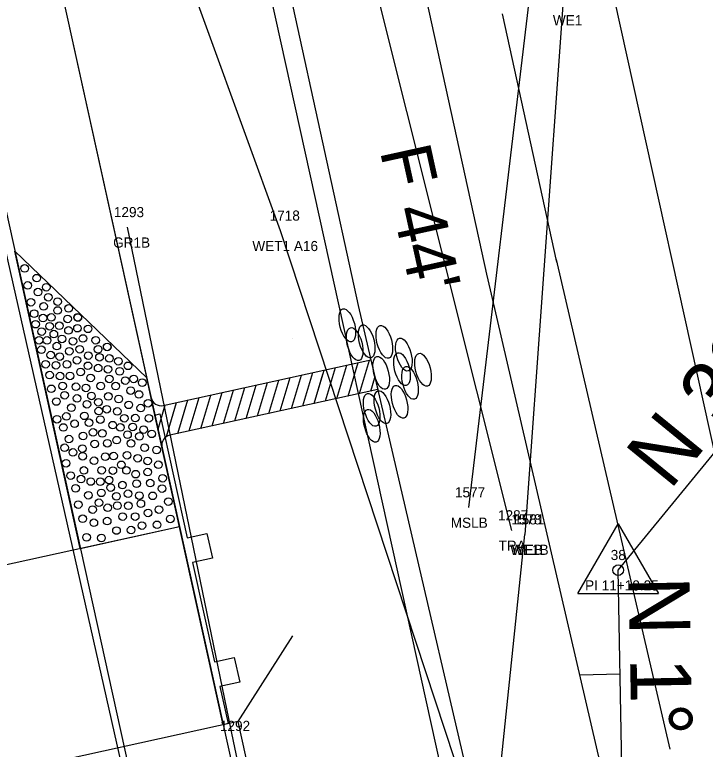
# Model space of a CAD drawing. Extents: x 2520975 to 2526538, y 881018 to 888064.
# Drawn here: x 2523776.7 to 2523844.7, y 885185.4 to 885257.8 of the extents above; entities that cross this region are included whole.
import ezdxf

# ---------------------------------------------------------------- set-up
doc = ezdxf.new("R2010")
doc.units = 0
for name, color, linetype in [('RD_EV_JurisArea', 7, 'Continuous'), ('RD_EX_DV_Prop', 7, 'Continuous'), ('RD_EX_GuardRail', 7, 'Continuous'), ('RD_EX_GuardRail_txCode', 7, 'Continuous'), ('RD_EX_H2O', 7, 'Continuous'), ('RD_EX_H2O_txCode', 7, 'Continuous'), ('RD_EX_H2O_WetLd_txCode', 7, 'Continuous'), ('RD_EX_Misc', 7, 'Continuous'), ('RD_EX_Misc_txCode', 7, 'Continuous'), ('RD_EX_Road', 7, 'Continuous'), ('RD_EX_RW', 7, 'Continuous'), ('RD_EX_VEG', 7, 'Continuous'), ('RD_EX_VEG_txCode', 7, 'Continuous'), ('RD_HC_Cl', 7, 'Continuous'), ('RD_HC_Data', 7, 'Continuous'), ('RD_HC_Data_Tic', 7, 'Continuous'), ('RD_HC_txCode', 7, 'Continuous'), ('RD_PD_BCA', 7, 'Continuous'), ('RD_PD_Bridge', 7, 'Continuous'), ('RD_PD_CstnLmt', 7, 'Continuous'), ('RD_PD_DR_ErosCtrl', 7, 'Continuous'), ('RD_PD_Final_TrvlWay', 7, 'Continuous'), ('RD_PD_GR', 7, 'Continuous'), ('RD_PD_PaveShd', 7, 'Continuous'), ('RD_SMD_Locator', 7, 'Continuous')]:
    doc.layers.add(name, color=color, linetype=linetype)

# ---------------------------------------------------------------- blocks, each defined once
blk = doc.blocks.new('TBC1')
at = {"layer": 'RD_PD_GR'}
blk.add_lwpolyline([(12.5, 2.5), (15, 2.5), (15, 0.492), (25, 0.492), (25, 2.5), (27.5, 2.5), (27.5, 0.492), (31.25, 0.492), (31.25, 0), (0, 0), (0, 0.492), (12.5, 0.492)], close=True, dxfattribs=at)

msp = doc.modelspace()

# ---------------------------------------------------------------- linework, layer by layer
at = {"layer": 'RD_EV_JurisArea'}
msp.add_lwpolyline([(2523761.167, 885134.03), (2523808.209, 885149.207), (2523821.914, 885178.637), (2523802.851, 885236.548), (2523777.81, 885305.562), (2523748.196, 885444.322), (2523730.68, 885516.876), (2523708.637, 885617.3), (2523698.714, 885662.019), (2523727.827, 885665.815), (2523757.297, 885671.751)], dxfattribs=at)
at = {"layer": 'RD_EX_DV_Prop'}
msp.add_line((2523830.151, 885284.722), (2523894.666, 884991.741), dxfattribs=at)
at = {"layer": 'RD_EX_GuardRail'}
msp.add_lwpolyline([(2523803.786, 885159.912), (2523798.239, 885186.256), (2523787.795, 885236.892)], dxfattribs=at)
at = {"layer": 'RD_EX_H2O'}
for points in [[(2524064.856, 885165.15), (2524036.37, 885213.784), (2524057.223, 885252.722), (2524031.954, 885291.634), (2523983.255, 885326.297), (2523940.609, 885311.826), (2523904.837, 885305.013), (2523874.983, 885272.096), (2523850.319, 885280.241), (2523830.665, 885258.799), (2523826.928, 885206.612)], [(2523738.909, 885147.498), (2523743.695, 885138.843), (2523816.359, 885152.29), (2523822.427, 885163.299), (2523826.928, 885206.612)]]:
    msp.add_lwpolyline(points, dxfattribs=at)
at = {"layer": 'RD_EX_Misc'}
msp.add_lwpolyline([(2524066.305, 885165.351), (2524037.301, 885214.147), (2524057.946, 885253.065), (2524039.523, 885283.168), (2524032.922, 885292.565), (2523983.53, 885327.977), (2523940.238, 885313.274), (2523904.134, 885306.246), (2523874.86, 885272.666), (2523849.958, 885282.507), (2523827.651, 885261.934), (2523821.385, 885209.277)], dxfattribs=at)
at = {"layer": 'RD_EX_Road'}
msp.add_line((2523792.777, 885159.311), (2523771.239, 885254.787), dxfattribs=at)
at = {"layer": 'RD_EX_RW'}
msp.add_line((2523830.151, 885284.719), (2523894.667, 884991.738), dxfattribs=at)
at = {"layer": 'RD_EX_VEG'}
msp.add_lwpolyline([(2523825.623, 885207.01), (2523811.867, 885262.105), (2523733.022, 885654.224), (2523687.107, 885876.236)], dxfattribs=at)
at = {"layer": 'RD_HC_Cl'}
for p, q in [((2523662.651, 885798.932), (2524219.244, 883271.288)), ((2523836.106, 885203.1), (2523883.663, 885261.233)), ((2523837.18, 885148.323), (2523836.106, 885203.1))]:
    msp.add_line(p, q, dxfattribs=at)
at = {"layer": 'RD_HC_Data'}
for p, q in [((2523832.135, 885200.807), (2523836.107, 885207.686)), ((2523836.107, 885207.686), (2523840.076, 885200.807)), ((2523832.135, 885200.807), (2523840.076, 885200.807))]:
    msp.add_line(p, q, dxfattribs=at)
msp.add_circle((2523836.106, 885203.1), 0.529, dxfattribs=at)
at = {"layer": 'RD_HC_Data_Tic'}
msp.add_line((2523836.307, 885192.845), (2523832.308, 885192.766), dxfattribs=at)
at = {"layer": 'RD_PD_BCA'}
for p, q in [((2523824.701, 885257.92), (2523830.049, 885233.47)), ((2523829.993, 885233.72), (2523841.201, 885185.449))]:
    msp.add_line(p, q, dxfattribs=at)
at = {"layer": 'RD_PD_Bridge'}
for p, q in [((2523749.936, 885197.941), (2523792.907, 885207.403)), ((2523797.208, 885187.871), (2523792.907, 885207.403)), ((2523798.673, 885188.194), (2523804.058, 885196.62))]:
    msp.add_line(p, q, dxfattribs=at)
for points in [[(2523798.673, 885188.194), (2523752.772, 885178.086)], [(2523826.629, 885061.235), (2523798.673, 885188.194)]]:
    msp.add_lwpolyline(points, dxfattribs=at)
at = {"layer": 'RD_PD_CstnLmt'}
for p, q in [((2523789.142, 885326.887), (2523810.511, 885229.196)), ((2523810.511, 885229.196), (2523821.719, 885180.926))]:
    msp.add_line(p, q, dxfattribs=at)
at = {"layer": 'RD_PD_DR_ErosCtrl'}
for p, q in [((2523801.841, 885329.665), (2523823.211, 885231.974)), ((2523823.174, 885232.137), (2523834.383, 885183.866))]:
    msp.add_line(p, q, dxfattribs=at)
at = {"layer": 'RD_PD_Final_TrvlWay'}
for p, q in [((2523712.872, 885663.865), (2524066.737, 884056.869)), ((2523720.239, 885490.907), (2524037.438, 884050.417))]:
    msp.add_line(p, q, dxfattribs=at)
at = {"layer": 'RD_PD_GR'}
msp.add_line((2523742.101, 885438.126), (2523790.488, 885218.39), dxfattribs=at)
at = {"layer": 'RD_PD_PaveShd'}
for p, q in [((2523776.689, 885234.551), (2523789.681, 885222.052)), ((2523783.141, 885205.253), (2523776.689, 885234.551)), ((2523791.303, 885219.337), (2523811.757, 885223.83)), ((2523808.404, 885220.022), (2523809.388, 885223.309)), ((2523808.404, 885220.022), (2523809.388, 885223.309)), ((2523809.521, 885220.267), (2523810.505, 885223.555)), ((2523810.638, 885220.513), (2523811.622, 885223.8)), ((2523810.638, 885220.513), (2523811.622, 885223.8)), ((2523811.757, 885223.83), (2523812.436, 885220.907)), ((2523806.169, 885219.531), (2523807.153, 885222.819)), ((2523807.287, 885219.776), (2523808.271, 885223.064)), ((2523807.287, 885219.776), (2523808.271, 885223.064)), ((2523809.521, 885220.267), (2523810.384, 885223.15)), ((2523790.326, 885219.122), (2523789.681, 885222.052)), ((2523802.818, 885218.795), (2523803.801, 885222.082)), ((2523802.818, 885218.795), (2523803.801, 885222.082)), ((2523803.935, 885219.04), (2523804.919, 885222.328)), ((2523803.935, 885219.04), (2523804.919, 885222.328)), ((2523805.052, 885219.286), (2523806.036, 885222.573)), ((2523805.052, 885219.286), (2523806.036, 885222.573)), ((2523806.169, 885219.531), (2523807.032, 885222.413)), ((2523811.756, 885220.758), (2523812.158, 885222.103)), ((2523811.756, 885220.758), (2523812.158, 885222.103)), ((2523799.466, 885218.058), (2523800.45, 885221.346)), ((2523799.466, 885218.058), (2523800.45, 885221.346)), ((2523800.583, 885218.304), (2523801.567, 885221.591)), ((2523800.583, 885218.304), (2523801.567, 885221.591)), ((2523801.7, 885218.549), (2523802.684, 885221.837)), ((2523801.7, 885218.549), (2523802.684, 885221.837)), ((2523812.436, 885220.907), (2523791.949, 885216.407)), ((2523796.114, 885217.322), (2523797.098, 885220.61)), ((2523797.231, 885217.568), (2523798.215, 885220.855)), ((2523797.231, 885217.568), (2523798.215, 885220.855)), ((2523798.348, 885217.813), (2523799.332, 885221.101)), ((2523798.348, 885217.813), (2523799.332, 885221.101)), ((2523792.762, 885216.586), (2523793.746, 885219.874)), ((2523792.762, 885216.586), (2523793.746, 885219.874)), ((2523793.879, 885216.831), (2523794.863, 885220.119)), ((2523793.879, 885216.831), (2523794.863, 885220.119)), ((2523794.997, 885217.077), (2523795.981, 885220.364)), ((2523794.997, 885217.077), (2523795.981, 885220.364)), ((2523790.971, 885216.193), (2523790.326, 885219.122)), ((2523790.796, 885216.992), (2523791.511, 885219.383)), ((2523791.625, 885216.273), (2523792.629, 885219.628)), ((2523792.907, 885207.403), (2523790.971, 885216.193)), ((2523783.141, 885205.253), (2523792.907, 885207.403))]:
    msp.add_line(p, q, dxfattribs=at)
for centre in [(2523777.666, 885232.841), (2523778.856, 885231.882), (2523778.856, 885231.882), (2523777.968, 885231.167), (2523777.968, 885231.167), (2523779.793, 885230.988), (2523779.793, 885230.988), (2523778.977, 885230.511), (2523778.977, 885230.511), (2523778.285, 885229.502), (2523778.285, 885229.502), (2523779.981, 885229.998), (2523779.981, 885229.998), (2523780.904, 885229.572), (2523779.522, 885229.096), (2523779.522, 885229.096), (2523781.994, 885228.895), (2523781.994, 885228.895), (2523778.599, 885228.38), (2523778.599, 885228.38), (2523780.286, 885228.017), (2523780.286, 885228.017), (2523780.902, 885228.695), (2523780.902, 885228.695), (2523782.878, 885228.022), (2523782.902, 885227.998), (2523778.738, 885227.346), (2523778.738, 885227.346), (2523779.472, 885227.942), (2523779.472, 885227.942), (2523781.895, 885227.867), (2523781.895, 885227.867), (2523779.333, 885226.612), (2523779.333, 885226.612), (2523780.119, 885227.145), (2523780.119, 885227.145), (2523781.078, 885227.19), (2523781.078, 885227.19), (2523781.98, 885226.731), (2523781.98, 885226.731), (2523782.865, 885226.95), (2523782.865, 885226.95), (2523783.909, 885226.886), (2523783.909, 885226.886), (2523780.537, 885226.371), (2523780.537, 885226.371), (2523781.34, 885225.894), (2523781.34, 885225.894), (2523783.396, 885225.935), (2523783.396, 885225.935), (2523779.08, 885225.767), (2523779.08, 885225.767), (2523779.876, 885225.741), (2523779.876, 885225.741), (2523780.831, 885225.184), (2523780.831, 885225.184), (2523782.41, 885225.668), (2523782.41, 885225.668), (2523784.667, 885225.761), (2523784.667, 885225.761), (2523785.786, 885225.108), (2523785.797, 885225.105), (2523779.317, 885224.822), (2523779.317, 885224.822), (2523782.05, 885224.678), (2523782.05, 885224.678), (2523783.094, 885224.873), (2523783.094, 885224.873), (2523784.896, 885224.866), (2523784.896, 885224.866), (2523780.235, 885224.299), (2523780.235, 885224.299), (2523781.114, 885224.154), (2523781.114, 885224.154), (2523782.805, 885223.79), (2523782.805, 885223.79), (2523783.924, 885224.247), (2523783.924, 885224.247), (2523785.033, 885224.081), (2523785.033, 885224.081), (2523786.014, 885223.973), (2523786.014, 885223.973), (2523786.9, 885223.688), (2523786.9, 885223.688), (2523779.722, 885223.401), (2523779.722, 885223.401), (2523780.743, 885223.296), (2523780.743, 885223.296), (2523781.821, 885223.387), (2523781.821, 885223.387), (2523783.893, 885223.243), (2523783.893, 885223.243), (2523784.902, 885223.024), (2523784.902, 885223.024), (2523787.841, 885223.241), (2523787.841, 885223.241), (2523780.123, 885222.324), (2523780.123, 885222.324), (2523781.15, 885222.234), (2523781.15, 885222.234), (2523782.128, 885222.251), (2523782.128, 885222.251), (2523783.172, 885222.632), (2523783.172, 885222.632), (2523785.859, 885222.903), (2523785.859, 885222.903), (2523787.018, 885222.701), (2523787.018, 885222.701), (2523784.155, 885222.048), (2523784.155, 885222.048), (2523785.988, 885221.955), (2523785.988, 885221.955), (2523787.572, 885221.791), (2523787.572, 885221.791), (2523788.407, 885221.955), (2523788.407, 885221.955), (2523789.246, 885221.58), (2523789.246, 885221.58), (2523789.246, 885221.58), (2523780.277, 885220.975), (2523780.277, 885220.975), (2523781.397, 885221.261), (2523781.397, 885221.261), (2523782.715, 885221.176), (2523782.715, 885221.176), (2523783.693, 885221.06), (2523783.693, 885221.06), (2523785.157, 885221.252), (2523785.157, 885221.252), (2523786.624, 885221.248), (2523786.624, 885221.248), (2523788.104, 885220.805), (2523788.104, 885220.805), (2523781.597, 885220.343), (2523781.597, 885220.343), (2523782.826, 885220.027), (2523782.826, 885220.027), (2523784.244, 885220.275), (2523784.244, 885220.275), (2523785.903, 885220.223), (2523785.903, 885220.223), (2523788.918, 885220.417), (2523788.918, 885220.417), (2523780.792, 885219.725), (2523780.792, 885219.725), (2523783.793, 885219.459), (2523783.793, 885219.459), (2523784.927, 885219.657), (2523784.927, 885219.657), (2523786.923, 885219.97), (2523786.923, 885219.97), (2523787.909, 885219.396), (2523787.909, 885219.396), (2523789.821, 885219.548), (2523789.821, 885219.548), (2523782.262, 885219.11), (2523782.262, 885219.11), (2523784.954, 885218.78), (2523784.954, 885218.78), (2523785.754, 885218.965), (2523785.754, 885218.965), (2523786.785, 885218.75), (2523786.785, 885218.75), (2523789.097, 885219.082), (2523789.097, 885219.082), (2523780.846, 885217.973), (2523780.846, 885217.973), (2523781.777, 885218.252), (2523781.777, 885218.252), (2523783.552, 885218.311), (2523783.552, 885218.311), (2523785.118, 885217.946), (2523785.118, 885217.946), (2523787.474, 885218.079), (2523787.474, 885218.079), (2523788.551, 885218.087), (2523788.551, 885218.087), (2523789.893, 885218.079), (2523789.893, 885218.079), (2523781.472, 885217.165), (2523781.472, 885217.165), (2523782.574, 885217.528), (2523782.574, 885217.528), (2523784.012, 885217.636), (2523784.012, 885217.636), (2523786.338, 885217.395), (2523786.338, 885217.395), (2523787.097, 885217.168), (2523787.097, 885217.168), (2523788.312, 885217.218), (2523788.312, 885217.218), (2523784.4, 885216.674), (2523784.4, 885216.674), (2523785.31, 885216.586), (2523785.31, 885216.586), (2523787.793, 885216.457), (2523787.793, 885216.457), (2523789.373, 885216.963), (2523789.373, 885216.963), (2523790.175, 885216.537), (2523790.175, 885216.537), (2523782.019, 885216.02), (2523782.019, 885216.02), (2523783.413, 885216.326), (2523783.413, 885216.326), (2523786.722, 885215.916), (2523786.722, 885215.916), (2523788.963, 885216.293), (2523788.963, 885216.293), (2523781.595, 885215.164), (2523783.351, 885215.084), (2523783.351, 885215.084), (2523784.565, 885215.548), (2523784.565, 885215.548), (2523785.804, 885215.611), (2523785.804, 885215.611), (2523788.136, 885215.596), (2523788.136, 885215.596), (2523789.478, 885215.174), (2523789.478, 885215.174), (2523782.41, 885214.704), (2523782.41, 885214.704), (2523783.374, 885214.333), (2523783.374, 885214.333), (2523785.594, 885214.289), (2523785.594, 885214.289), (2523786.419, 885214.352), (2523786.419, 885214.352), (2523787.746, 885214.431), (2523787.746, 885214.431), (2523790.65, 885214.948), (2523790.65, 885214.948), (2523781.741, 885213.643), (2523781.741, 885213.643), (2523784.503, 885213.892), (2523784.503, 885213.892), (2523788.795, 885214.138), (2523788.795, 885214.138), (2523789.769, 885213.867), (2523789.769, 885213.867), (2523783.492, 885212.933), (2523783.492, 885212.933), (2523785.234, 885212.949), (2523785.234, 885212.949), (2523786.348, 885212.919), (2523786.348, 885212.919), (2523787.173, 885213.486), (2523787.173, 885213.486), (2523787.691, 885212.938), (2523787.691, 885212.938), (2523790.833, 885213.487), (2523790.833, 885213.487), (2523782.204, 885212.429), (2523782.204, 885212.429), (2523783.214, 885212.079), (2523783.214, 885212.079), (2523788.593, 885212.565), (2523788.593, 885212.565), (2523789.79, 885212.765), (2523789.79, 885212.765), (2523791.249, 885212.164), (2523791.249, 885212.164), (2523784.178, 885211.839), (2523784.178, 885211.839), (2523785.102, 885211.825), (2523785.102, 885211.825), (2523785.978, 885211.982), (2523785.978, 885211.982), (2523787.297, 885211.485), (2523787.297, 885211.485), (2523788.684, 885211.628), (2523788.684, 885211.628), (2523790.024, 885211.682), (2523790.024, 885211.682), (2523782.68, 885211.17), (2523782.68, 885211.17), (2523785.213, 885210.723), (2523785.213, 885210.723), (2523786.142, 885211.239), (2523787.851, 885210.633), (2523787.851, 885210.633), (2523791.192, 885211.147), (2523791.192, 885211.147), (2523783.942, 885210.483), (2523783.942, 885210.483), (2523786.703, 885210.381), (2523786.703, 885210.381), (2523788.957, 885210.451), (2523788.957, 885210.451), (2523790.274, 885210.429), (2523790.274, 885210.429), (2523782.943, 885209.562), (2523782.943, 885209.562), (2523784.978, 885209.753), (2523784.978, 885209.753), (2523785.848, 885209.251), (2523785.848, 885209.251), (2523786.792, 885209.459), (2523786.792, 885209.459), (2523787.872, 885209.452), (2523787.872, 885209.452), (2523789.105, 885209.656), (2523789.105, 885209.656), (2523791.821, 885209.863), (2523791.821, 885209.863), (2523784.349, 885209.079), (2523784.349, 885209.079), (2523789.812, 885208.748), (2523789.812, 885208.748), (2523790.88, 885209.07), (2523790.88, 885209.07), (2523783.374, 885208.172), (2523783.374, 885208.172), (2523784.477, 885207.78), (2523784.477, 885207.78), (2523785.788, 885207.946), (2523785.788, 885207.946), (2523787.304, 885208.382), (2523787.304, 885208.382), (2523788.545, 885208.383), (2523788.545, 885208.383), (2523792.011, 885208.152), (2523792.011, 885208.152), (2523792.011, 885208.152), (2523786.707, 885207.01), (2523786.707, 885207.01), (2523788.147, 885207.055), (2523788.147, 885207.055), (2523789.211, 885207.501), (2523789.211, 885207.501), (2523790.7, 885207.573), (2523790.7, 885207.573), (2523783.756, 885206.341), (2523783.756, 885206.341), (2523785.225, 885206.274), (2523785.225, 885206.274)]:
    msp.add_circle(centre, 0.375, dxfattribs=at)
for centre, start, end in [((2523791.088, 885220.314), 192.41848, 282.38886), ((2523792.163, 885215.431), 102.38886, 192.41848)]:
    msp.add_arc(centre, 1, start, end, dxfattribs=at)
for centre in [(2523809.435, 885227.232), (2523810.164, 885225.383), (2523811.34, 885225.65), (2523811.34, 885225.65), (2523813.084, 885225.604), (2523813.084, 885225.604), (2523815.003, 885224.349), (2523815.003, 885224.349), (2523812.773, 885222.548), (2523812.773, 885222.548), (2523814.822, 885222.914), (2523814.822, 885222.914), (2523816.892, 885222.854), (2523816.892, 885222.854), (2523815.615, 885221.56), (2523815.615, 885221.56), (2523814.581, 885219.698), (2523814.581, 885219.698), (2523811.838, 885218.904), (2523811.838, 885218.904), (2523812.892, 885219.169), (2523812.892, 885219.169), (2523811.845, 885217.332), (2523811.845, 885217.332)]:
    msp.add_ellipse(centre, major_axis=(-0.426, 1.616), ratio=0.429445, dxfattribs=at)
at = {"layer": 'RD_SMD_Locator'}
for centre in [(2523787.795, 885236.892), (2523802.851, 885236.548), (2523804.069, 885225.964), (2523821.385, 885209.277), (2523825.623, 885207.01), (2523826.928, 885206.612), (2523826.928, 885206.612), (2523836.106, 885203.1), (2523798.239, 885186.256)]:
    msp.add_circle(centre, 0.001, dxfattribs=at)

# ---------------------------------------------------------------- block references
at = {"layer": 'RD_PD_Bridge', "rotation": -77.58151740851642}
msp.add_blockref('TBC1', (2523790.488, 885218.39), dxfattribs=at)

# ---------------------------------------------------------------- texts
at = {"layer": 'RD_EX_GuardRail_txCode'}
for s, p in [('1293', (2523786.449, 885237.892)), ('GR1B', (2523786.378, 885234.892)), ('1292', (2523796.892, 885187.256))]:
    msp.add_text(s, height=1, dxfattribs=at).set_placement(p)
at = {"layer": 'RD_EX_H2O_txCode'}
for s, p in [('WE1', (2523829.681, 885256.799)), ('1578', (2523825.582, 885207.612)), ('1581', (2523825.865, 885207.612)), ('WE1B', (2523825.471, 885204.612)), ('WEB', (2523825.637, 885204.612))]:
    msp.add_text(s, height=1, dxfattribs=at).set_placement(p)
at = {"layer": 'RD_EX_H2O_WetLd_txCode'}
for s, p in [('1718', (2523801.788, 885237.548)), ('WET1 A16', (2523800.087, 885234.548))]:
    msp.add_text(s, height=1, dxfattribs=at).set_placement(p)
at = {"layer": 'RD_EX_Misc_txCode'}
for s, p in [('1577', (2523820.038, 885210.277)), ('MSLB', (2523819.621, 885207.277))]:
    msp.add_text(s, height=1, dxfattribs=at).set_placement(p)
at = {"layer": 'RD_EX_VEG_txCode'}
for s, p in [('1287', (2523824.276, 885208.01)), ('TRA', (2523824.339, 885205.01))]:
    msp.add_text(s, height=1, dxfattribs=at).set_placement(p)
at = {"layer": 'RD_HC_Data'}
for s, rotation, p in [('N 39%%d 17\' 08" E', 50.71443, (2523841.195, 885210.9)), ('N 1%%d 07\' 21" W', 271.12261, (2523837.119, 885202.44))]:
    msp.add_text(s, height=6, rotation=rotation, dxfattribs=at).set_placement(p)
at = {"layer": 'RD_HC_txCode'}
for s, p in [('38', (2523835.374, 885204.1)), ('PI 11+10.25', (2523832.854, 885201.1))]:
    msp.add_text(s, height=1, dxfattribs=at).set_placement(p)
at = {"layer": 'RD_PD_CstnLmt'}
msp.add_text("F 44'", height=5, rotation=282.41848, dxfattribs=at).set_placement((2523812.626, 885244.447))

doc.saveas('drawing.dxf')
